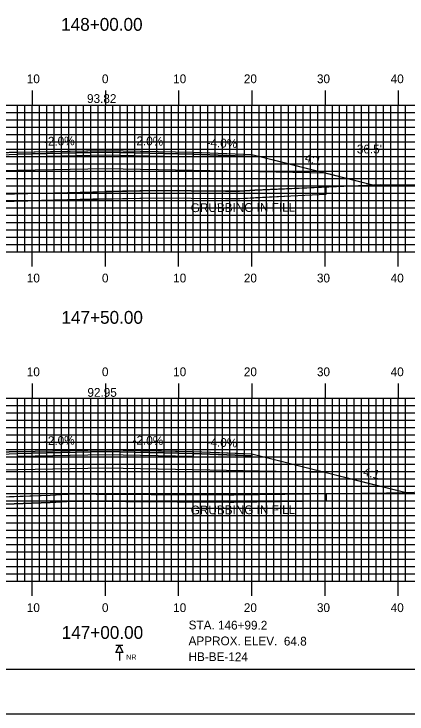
# Model space of a CAD drawing. Extents: x 1777925 to 1778268, y 442591 to 442811.
# Drawn here: x 1778078.3 to 1778132, y 442590.5 to 442686.1 of the extents above; entities that cross this region are included whole.
import ezdxf

# ---------------------------------------------------------------- set-up
doc = ezdxf.new("R2010")
doc.units = 0
for name, color, linetype in [('ANNOTATION', 7, 'Continuous'), ('BORDER', 7, 'Continuous'), ('BORING - NO REFUSAL', 7, 'Continuous'), ('D_Roadway_Centerline', 7, 'Continuous'), ('D_Roadway_Centerline_Text', 7, 'Continuous'), ('D_Roadway_Edge_Shoulder', 7, 'Continuous'), ('D_Roadway_Edge_TW', 7, 'Continuous'), ('D_Roadway_Pavement', 7, 'Continuous'), ('D_Roadway_SlopeLines', 7, 'Continuous'), ('D_Roadway_SubGrade', 7, 'Continuous'), ('D_Text_Standard', 7, 'Continuous'), ('GRUBBING IN FILL', 7, 'Continuous'), ('H_V ANNOTATION', 7, 'Continuous'), ('MAJOR', 7, 'Continuous'), ('MINOR', 7, 'Continuous'), ('PLOT BOUNDARY', 7, 'Continuous'), ('S_Roadway_Centerline', 7, 'Continuous')]:
    doc.layers.add(name, color=color, linetype=linetype)

msp = doc.modelspace()

# ---------------------------------------------------------------- linework, layer by layer
at = {"layer": 'BORDER'}
msp.add_lwpolyline([(1777941.19, 442596.665), (1778261.19, 442596.665), (1778261.19, 442806.665), (1777941.19, 442806.665)], close=True, dxfattribs=at)
at = {"layer": 'BORING - NO REFUSAL'}
for p, q in [((1778093.17, 442599.883), (1778092.21, 442599.883)), ((1778092.69, 442598.924), (1778092.69, 442597.865))]:
    msp.add_line(p, q, dxfattribs=at)
msp.add_lwpolyline([(1778092.69, 442599.883), (1778093.17, 442598.924), (1778092.21, 442598.924)], close=True, dxfattribs=at)
at = {"layer": 'D_Roadway_Centerline'}
for points in [[(1778047.792, 442661.178), (1778058.79, 442663.927), (1778059.609, 442664.132), (1778060.616, 442664.384), (1778070.79, 442666.927), (1778072.648, 442667.002), (1778078.79, 442667.247), (1778085.551, 442667.382), (1778090.79, 442667.487), (1778102.79, 442667.247), (1778110.79, 442666.927), (1778115.943, 442665.639), (1778120.963, 442664.384), (1778121.24, 442664.315), (1778127.328, 442662.793)], [(1778043.66, 442619.27), (1778050.556, 442620.994), (1778058.789, 442623.052), (1778058.79, 442623.052), (1778060.591, 442623.503), (1778060.617, 442623.509), (1778061.603, 442623.756), (1778070.79, 442626.052), (1778078.79, 442626.372), (1778090.79, 442626.612), (1778096.258, 442626.503), (1778102.79, 442626.372), (1778108.725, 442626.135), (1778110.79, 442626.052), (1778120.964, 442623.509), (1778126.145, 442622.214), (1778131.883, 442620.779)]]:
    msp.add_lwpolyline(points, dxfattribs=at)
at = {"layer": 'D_Roadway_Edge_Shoulder'}
for points in [[(1778078.79, 442667.247), (1778070.79, 442666.927), (1778070.79, 442666.677), (1778078.79, 442666.997)], [(1778102.79, 442667.247), (1778110.79, 442666.927), (1778110.79, 442666.677), (1778102.79, 442666.997)], [(1778078.79, 442626.372), (1778070.79, 442626.052), (1778070.79, 442625.802), (1778078.79, 442626.122)], [(1778102.79, 442626.372), (1778110.79, 442626.052), (1778110.79, 442625.802), (1778102.79, 442626.122)]]:
    msp.add_lwpolyline(points, close=True, dxfattribs=at)
at = {"layer": 'D_Roadway_Edge_TW'}
for points in [[(1778078.79, 442666.997), (1778078.79, 442667.247), (1778090.79, 442667.487), (1778102.79, 442667.247), (1778102.79, 442666.997), (1778090.79, 442667.237)], [(1778078.79, 442626.122), (1778078.79, 442626.372), (1778090.79, 442626.612), (1778102.79, 442626.372), (1778102.79, 442626.122), (1778090.79, 442626.362)]]:
    msp.add_lwpolyline(points, close=True, dxfattribs=at)
at = {"layer": 'D_Roadway_Pavement'}
for points in [[(1778078.79, 442666.581), (1778078.79, 442666.997), (1778090.79, 442667.237), (1778102.79, 442666.997), (1778102.79, 442666.581), (1778090.79, 442666.821)], [(1778078.79, 442625.706), (1778078.79, 442626.122), (1778090.79, 442626.362), (1778102.79, 442626.122), (1778102.79, 442625.706), (1778090.79, 442625.946)]]:
    msp.add_lwpolyline(points, close=True, dxfattribs=at)
at = {"layer": 'D_Roadway_SlopeLines'}
for points in [[(1778110.79, 442666.927), (1778120.963, 442664.384), (1778127.328, 442662.793)], [(1778110.79, 442626.052), (1778120.964, 442623.509), (1778131.883, 442620.779)]]:
    msp.add_lwpolyline(points, dxfattribs=at)
at = {"layer": 'D_Roadway_SubGrade'}
for points in [[(1778078.79, 442664.747), (1778060.616, 442664.384), (1778070.79, 442666.927), (1778070.79, 442666.677), (1778078.79, 442666.997), (1778090.79, 442667.237), (1778102.79, 442666.997), (1778110.79, 442666.677), (1778110.79, 442666.927), (1778120.963, 442664.384), (1778102.79, 442664.747), (1778090.79, 442664.987)], [(1778078.79, 442623.872), (1778060.617, 442623.509), (1778070.79, 442626.052), (1778070.79, 442625.802), (1778078.79, 442626.122), (1778090.79, 442626.362), (1778102.79, 442626.122), (1778110.79, 442625.802), (1778110.79, 442626.052), (1778120.964, 442623.509), (1778102.79, 442623.872), (1778090.79, 442624.112)]]:
    msp.add_lwpolyline(points, close=True, dxfattribs=at)
at = {"layer": 'GRUBBING IN FILL'}
for p, q in [((1778120.963, 442661.499), (1778120.963, 442662.499)), ((1778120.963, 442661.499), (1778120.963, 442662.499)), ((1778120.964, 442620.638), (1778120.964, 442619.638)), ((1778120.964, 442620.638), (1778120.964, 442619.638))]:
    msp.add_line(p, q, dxfattribs=at)
for points in [[(1778090.79, 442660.86), (1778097.822, 442661.026), (1778107.179, 442660.909), (1778109.141, 442660.925), (1778110.206, 442660.988), (1778116.117, 442661.275), (1778120.963, 442661.499), (1778120.963, 442662.499), (1778119.806, 442662.446), (1778111.218, 442662.05), (1778109.107, 442661.925), (1778107.182, 442661.909), (1778097.817, 442662.026), (1778090.79, 442661.86)], [(1778090.79, 442660.86), (1778097.822, 442661.026), (1778107.179, 442660.909), (1778109.141, 442660.925), (1778110.206, 442660.988), (1778116.117, 442661.275), (1778120.963, 442661.499), (1778120.963, 442662.499), (1778119.806, 442662.446), (1778111.218, 442662.05), (1778109.107, 442661.925), (1778107.182, 442661.909), (1778097.817, 442662.026), (1778090.79, 442661.86)], [(1778060.616, 442661.205), (1778063.326, 442661.288), (1778065.358, 442661.247), (1778074.613, 442661.472), (1778083.869, 442661.697), (1778090.79, 442661.86), (1778090.79, 442660.86), (1778083.893, 442660.697), (1778074.626, 442660.472), (1778065.36, 442660.247), (1778060.616, 442660.205)], [(1778060.616, 442661.205), (1778063.326, 442661.288), (1778065.358, 442661.247), (1778074.613, 442661.472), (1778083.869, 442661.697), (1778090.79, 442661.86), (1778090.79, 442660.86), (1778083.893, 442660.697), (1778074.626, 442660.472), (1778065.36, 442660.247), (1778060.616, 442660.205)], [(1778060.617, 442619.76), (1778060.942, 442619.759), (1778062.934, 442619.752), (1778067.528, 442619.88), (1778072.121, 442620.007), (1778077.667, 442620.223), (1778083.213, 442620.439), (1778086.468, 442620.6), (1778089.507, 442620.579), (1778090.27, 442620.574), (1778090.79, 442620.57), (1778090.79, 442619.57), (1778086.492, 442619.6), (1778085.99, 442619.572), (1778083.256, 442619.44), (1778072.155, 442619.007), (1778067.551, 442618.88), (1778061.781, 442618.756), (1778060.617, 442618.76)], [(1778060.617, 442619.76), (1778060.942, 442619.759), (1778062.934, 442619.752), (1778067.528, 442619.88), (1778072.121, 442620.007), (1778077.667, 442620.223), (1778083.213, 442620.439), (1778086.468, 442620.6), (1778089.507, 442620.579), (1778090.27, 442620.574), (1778090.79, 442620.57), (1778090.79, 442619.57), (1778086.492, 442619.6), (1778085.99, 442619.572), (1778083.256, 442619.44), (1778072.155, 442619.007), (1778067.551, 442618.88), (1778061.781, 442618.756), (1778060.617, 442618.76)], [(1778090.79, 442620.57), (1778097.046, 442620.527), (1778107.624, 442620.454), (1778118.76, 442620.607), (1778120.964, 442620.638), (1778120.964, 442619.638), (1778114.652, 442619.549), (1778108.339, 442619.459), (1778097.058, 442619.527), (1778090.79, 442619.57)], [(1778090.79, 442620.57), (1778097.046, 442620.527), (1778107.624, 442620.454), (1778118.76, 442620.607), (1778120.964, 442620.638), (1778120.964, 442619.638), (1778114.652, 442619.549), (1778108.339, 442619.459), (1778097.058, 442619.527), (1778090.79, 442619.57)]]:
    msp.add_lwpolyline(points, close=True, dxfattribs=at)
for points in [[(1778060.616, 442660.205), (1778063.331, 442660.288), (1778065.36, 442660.247), (1778083.893, 442660.697), (1778097.822, 442661.026), (1778107.179, 442660.909), (1778109.141, 442660.925), (1778111.271, 442661.052), (1778120.963, 442661.499)], [(1778060.616, 442660.205), (1778063.331, 442660.288), (1778065.36, 442660.247), (1778083.893, 442660.697), (1778097.822, 442661.026), (1778107.179, 442660.909), (1778109.141, 442660.925), (1778111.271, 442661.052), (1778120.963, 442661.499)], [(1778060.617, 442618.76), (1778062.946, 442618.752), (1778072.155, 442619.007), (1778083.256, 442619.44), (1778085.488, 442619.545), (1778086.492, 442619.6), (1778107.624, 442619.454), (1778108.339, 442619.459), (1778120.964, 442619.638)], [(1778060.617, 442618.76), (1778062.946, 442618.752), (1778072.155, 442619.007), (1778083.256, 442619.44), (1778085.488, 442619.545), (1778086.492, 442619.6), (1778107.624, 442619.454), (1778108.339, 442619.459), (1778120.964, 442619.638)]]:
    msp.add_lwpolyline(points, dxfattribs=at)
at = {"layer": 'MAJOR'}
for p, q in [((1778080.79, 442675.669), (1778080.79, 442673.665)), ((1778090.79, 442675.669), (1778090.79, 442673.665)), ((1778100.79, 442675.669), (1778100.79, 442673.665)), ((1778110.79, 442675.669), (1778110.79, 442673.665)), ((1778120.79, 442675.669), (1778120.79, 442673.665)), ((1778130.79, 442675.669), (1778130.79, 442673.665)), ((1777950.79, 442673.665), (1778230.79, 442673.665)), ((1777950.79, 442673.665), (1778230.79, 442673.665)), ((1778080.79, 442653.665), (1778080.79, 442673.665)), ((1778090.79, 442653.665), (1778090.79, 442673.665)), ((1778100.79, 442653.665), (1778100.79, 442673.665)), ((1778110.79, 442653.665), (1778110.79, 442673.665)), ((1778120.79, 442653.665), (1778120.79, 442673.665)), ((1778130.79, 442653.665), (1778130.79, 442673.665)), ((1777950.79, 442668.665), (1778230.79, 442668.665)), ((1777950.79, 442663.665), (1778230.79, 442663.665)), ((1777950.79, 442658.665), (1778230.79, 442658.665)), ((1777950.79, 442653.665), (1778230.79, 442653.665)), ((1777950.79, 442653.665), (1778230.79, 442653.665)), ((1778080.79, 442651.661), (1778080.79, 442653.665)), ((1778090.79, 442651.661), (1778090.79, 442653.665)), ((1778100.79, 442651.661), (1778100.79, 442653.665)), ((1778110.79, 442651.661), (1778110.79, 442653.665)), ((1778120.79, 442651.661), (1778120.79, 442653.665)), ((1778130.79, 442651.661), (1778130.79, 442653.665)), ((1778080.79, 442635.669), (1778080.79, 442633.665)), ((1778090.79, 442635.669), (1778090.79, 442633.665)), ((1778100.79, 442635.669), (1778100.79, 442633.665)), ((1778110.79, 442635.669), (1778110.79, 442633.665)), ((1778120.79, 442635.669), (1778120.79, 442633.665)), ((1778130.79, 442635.669), (1778130.79, 442633.665)), ((1777950.79, 442633.665), (1778230.79, 442633.665)), ((1777950.79, 442633.665), (1778230.79, 442633.665)), ((1778080.79, 442608.665), (1778080.79, 442633.665)), ((1778090.79, 442608.665), (1778090.79, 442633.665)), ((1778100.79, 442608.665), (1778100.79, 442633.665)), ((1778110.79, 442608.665), (1778110.79, 442633.665)), ((1778120.79, 442608.665), (1778120.79, 442633.665)), ((1778130.79, 442608.665), (1778130.79, 442633.665)), ((1777950.79, 442628.665), (1778230.79, 442628.665)), ((1777950.79, 442623.665), (1778230.79, 442623.665)), ((1777950.79, 442618.665), (1778230.79, 442618.665)), ((1777950.79, 442613.665), (1778230.79, 442613.665)), ((1777950.79, 442608.665), (1778230.79, 442608.665)), ((1777950.79, 442608.665), (1778230.79, 442608.665)), ((1778080.79, 442606.661), (1778080.79, 442608.665)), ((1778090.79, 442606.661), (1778090.79, 442608.665)), ((1778100.79, 442606.661), (1778100.79, 442608.665)), ((1778110.79, 442606.661), (1778110.79, 442608.665)), ((1778120.79, 442606.661), (1778120.79, 442608.665)), ((1778130.79, 442606.661), (1778130.79, 442608.665))]:
    msp.add_line(p, q, dxfattribs=at)
at = {"layer": 'MINOR'}
for p, q in [((1778078.79, 442653.665), (1778078.79, 442673.665)), ((1778079.79, 442653.665), (1778079.79, 442673.665)), ((1778081.79, 442653.665), (1778081.79, 442673.665)), ((1778082.79, 442653.665), (1778082.79, 442673.665)), ((1778083.79, 442653.665), (1778083.79, 442673.665)), ((1778084.79, 442653.665), (1778084.79, 442673.665)), ((1778085.79, 442653.665), (1778085.79, 442673.665)), ((1778086.79, 442653.665), (1778086.79, 442673.665)), ((1778087.79, 442653.665), (1778087.79, 442673.665)), ((1778088.79, 442653.665), (1778088.79, 442673.665)), ((1778089.79, 442653.665), (1778089.79, 442673.665)), ((1778091.79, 442653.665), (1778091.79, 442673.665)), ((1778092.79, 442653.665), (1778092.79, 442673.665)), ((1778093.79, 442653.665), (1778093.79, 442673.665)), ((1778094.79, 442653.665), (1778094.79, 442673.665)), ((1778095.79, 442653.665), (1778095.79, 442673.665)), ((1778096.79, 442653.665), (1778096.79, 442673.665)), ((1778097.79, 442653.665), (1778097.79, 442673.665)), ((1778098.79, 442653.665), (1778098.79, 442673.665)), ((1778099.79, 442653.665), (1778099.79, 442673.665)), ((1778101.79, 442653.665), (1778101.79, 442673.665)), ((1778102.79, 442653.665), (1778102.79, 442673.665)), ((1778103.79, 442653.665), (1778103.79, 442673.665)), ((1778104.79, 442653.665), (1778104.79, 442673.665)), ((1778105.79, 442653.665), (1778105.79, 442673.665)), ((1778106.79, 442653.665), (1778106.79, 442673.665)), ((1778107.79, 442653.665), (1778107.79, 442673.665)), ((1778108.79, 442653.665), (1778108.79, 442673.665)), ((1778109.79, 442653.665), (1778109.79, 442673.665)), ((1778111.79, 442653.665), (1778111.79, 442673.665)), ((1778112.79, 442653.665), (1778112.79, 442673.665)), ((1778113.79, 442653.665), (1778113.79, 442673.665)), ((1778114.79, 442653.665), (1778114.79, 442673.665)), ((1778115.79, 442653.665), (1778115.79, 442673.665)), ((1778116.79, 442653.665), (1778116.79, 442673.665)), ((1778117.79, 442653.665), (1778117.79, 442673.665)), ((1778118.79, 442653.665), (1778118.79, 442673.665)), ((1778119.79, 442653.665), (1778119.79, 442673.665)), ((1778121.79, 442653.665), (1778121.79, 442673.665)), ((1778122.79, 442653.665), (1778122.79, 442673.665)), ((1778123.79, 442653.665), (1778123.79, 442673.665)), ((1778124.79, 442653.665), (1778124.79, 442673.665)), ((1778125.79, 442653.665), (1778125.79, 442673.665)), ((1778126.79, 442653.665), (1778126.79, 442673.665)), ((1778127.79, 442653.665), (1778127.79, 442673.665)), ((1778128.79, 442653.665), (1778128.79, 442673.665)), ((1778129.79, 442653.665), (1778129.79, 442673.665)), ((1778131.79, 442653.665), (1778131.79, 442673.665)), ((1777950.79, 442672.665), (1778230.79, 442672.665)), ((1777950.79, 442671.665), (1778230.79, 442671.665)), ((1777950.79, 442670.665), (1778230.79, 442670.665)), ((1777950.79, 442669.665), (1778230.79, 442669.665)), ((1777950.79, 442667.665), (1778230.79, 442667.665)), ((1777950.79, 442666.665), (1778230.79, 442666.665)), ((1777950.79, 442665.665), (1778230.79, 442665.665)), ((1777950.79, 442664.665), (1778230.79, 442664.665)), ((1777950.79, 442662.665), (1778230.79, 442662.665)), ((1777950.79, 442661.665), (1778230.79, 442661.665)), ((1777950.79, 442660.665), (1778230.79, 442660.665)), ((1777950.79, 442659.665), (1778230.79, 442659.665)), ((1777950.79, 442657.665), (1778230.79, 442657.665)), ((1777950.79, 442656.665), (1778230.79, 442656.665)), ((1777950.79, 442655.665), (1778230.79, 442655.665)), ((1777950.79, 442654.665), (1778230.79, 442654.665)), ((1778078.79, 442608.665), (1778078.79, 442633.665)), ((1778079.79, 442608.665), (1778079.79, 442633.665)), ((1778081.79, 442608.665), (1778081.79, 442633.665)), ((1778082.79, 442608.665), (1778082.79, 442633.665)), ((1778083.79, 442608.665), (1778083.79, 442633.665)), ((1778084.79, 442608.665), (1778084.79, 442633.665)), ((1778085.79, 442608.665), (1778085.79, 442633.665)), ((1778086.79, 442608.665), (1778086.79, 442633.665)), ((1778087.79, 442608.665), (1778087.79, 442633.665)), ((1778088.79, 442608.665), (1778088.79, 442633.665)), ((1778089.79, 442608.665), (1778089.79, 442633.665)), ((1778091.79, 442608.665), (1778091.79, 442633.665)), ((1778092.79, 442608.665), (1778092.79, 442633.665)), ((1778093.79, 442608.665), (1778093.79, 442633.665)), ((1778094.79, 442608.665), (1778094.79, 442633.665)), ((1778095.79, 442608.665), (1778095.79, 442633.665)), ((1778096.79, 442608.665), (1778096.79, 442633.665)), ((1778097.79, 442608.665), (1778097.79, 442633.665)), ((1778098.79, 442608.665), (1778098.79, 442633.665)), ((1778099.79, 442608.665), (1778099.79, 442633.665)), ((1778101.79, 442608.665), (1778101.79, 442633.665)), ((1778102.79, 442608.665), (1778102.79, 442633.665)), ((1778103.79, 442608.665), (1778103.79, 442633.665)), ((1778104.79, 442608.665), (1778104.79, 442633.665)), ((1778105.79, 442608.665), (1778105.79, 442633.665)), ((1778106.79, 442608.665), (1778106.79, 442633.665)), ((1778107.79, 442608.665), (1778107.79, 442633.665)), ((1778108.79, 442608.665), (1778108.79, 442633.665)), ((1778109.79, 442608.665), (1778109.79, 442633.665)), ((1778111.79, 442608.665), (1778111.79, 442633.665)), ((1778112.79, 442608.665), (1778112.79, 442633.665)), ((1778113.79, 442608.665), (1778113.79, 442633.665)), ((1778114.79, 442608.665), (1778114.79, 442633.665)), ((1778115.79, 442608.665), (1778115.79, 442633.665)), ((1778116.79, 442608.665), (1778116.79, 442633.665)), ((1778117.79, 442608.665), (1778117.79, 442633.665)), ((1778118.79, 442608.665), (1778118.79, 442633.665)), ((1778119.79, 442608.665), (1778119.79, 442633.665)), ((1778121.79, 442608.665), (1778121.79, 442633.665)), ((1778122.79, 442608.665), (1778122.79, 442633.665)), ((1778123.79, 442608.665), (1778123.79, 442633.665)), ((1778124.79, 442608.665), (1778124.79, 442633.665)), ((1778125.79, 442608.665), (1778125.79, 442633.665)), ((1778126.79, 442608.665), (1778126.79, 442633.665)), ((1778127.79, 442608.665), (1778127.79, 442633.665)), ((1778128.79, 442608.665), (1778128.79, 442633.665)), ((1778129.79, 442608.665), (1778129.79, 442633.665)), ((1778131.79, 442608.665), (1778131.79, 442633.665)), ((1777950.79, 442632.665), (1778230.79, 442632.665)), ((1777950.79, 442631.665), (1778230.79, 442631.665)), ((1777950.79, 442630.665), (1778230.79, 442630.665)), ((1777950.79, 442629.665), (1778230.79, 442629.665)), ((1777950.79, 442627.665), (1778230.79, 442627.665)), ((1777950.79, 442626.665), (1778230.79, 442626.665)), ((1777950.79, 442625.665), (1778230.79, 442625.665)), ((1777950.79, 442624.665), (1778230.79, 442624.665)), ((1777950.79, 442622.665), (1778230.79, 442622.665)), ((1777950.79, 442621.665), (1778230.79, 442621.665)), ((1777950.79, 442620.665), (1778230.79, 442620.665)), ((1777950.79, 442619.665), (1778230.79, 442619.665)), ((1777950.79, 442617.665), (1778230.79, 442617.665)), ((1777950.79, 442616.665), (1778230.79, 442616.665)), ((1777950.79, 442615.665), (1778230.79, 442615.665)), ((1777950.79, 442614.665), (1778230.79, 442614.665)), ((1777950.79, 442612.665), (1778230.79, 442612.665)), ((1777950.79, 442611.665), (1778230.79, 442611.665)), ((1777950.79, 442610.665), (1778230.79, 442610.665)), ((1777950.79, 442609.665), (1778230.79, 442609.665))]:
    msp.add_line(p, q, dxfattribs=at)
at = {"layer": 'PLOT BOUNDARY'}
msp.add_lwpolyline([(1777925.003, 442590.547), (1778265.003, 442590.547), (1778265.003, 442810.547), (1777925.003, 442810.547)], close=True, dxfattribs=at)
at = {"layer": 'S_Roadway_Centerline'}
for points in [[(1777950.79, 442659.341), (1777957.637, 442659.573), (1777969.437, 442659.353), (1777970.922, 442659.383), (1777992.887, 442659.856), (1778004.185, 442659.95), (1778017.022, 442660.194), (1778027.551, 442660.534), (1778038.131, 442661.083), (1778040.821, 442661.181), (1778050.827, 442661.177), (1778061.024, 442661.218), (1778063.326, 442661.288), (1778065.358, 442661.247), (1778083.869, 442661.697), (1778097.817, 442662.026), (1778107.182, 442661.909), (1778109.107, 442661.925), (1778111.218, 442662.05), (1778128.394, 442662.842), (1778134.182, 442662.79)], [(1777950.79, 442617.395), (1777956.017, 442617.414), (1777972.056, 442617.846), (1777979.693, 442617.903), (1777987.767, 442618.089), (1777991.687, 442618.08), (1777995.058, 442618.124), (1778011.222, 442618.225), (1778018.028, 442618.392), (1778036.183, 442618.991), (1778037.813, 442619.081), (1778039.538, 442619.137), (1778058.95, 442619.765), (1778062.934, 442619.752), (1778072.121, 442620.007), (1778083.213, 442620.439), (1778085.437, 442620.544), (1778086.468, 442620.6), (1778107.624, 442620.454), (1778108.328, 442620.459), (1778129.191, 442620.755), (1778131.694, 442620.772), (1778142.049, 442621.162)]]:
    msp.add_lwpolyline(points, dxfattribs=at)

# ---------------------------------------------------------------- texts
at = {"layer": 'ANNOTATION'}
for s, rotation, p in [('-2.0%', 1.14576, (1778082.396, 442668.12)), ('-2.0%', 358.85424, (1778094.476, 442668.214)), ('-4.0%', 357.70947, (1778104.582, 442667.977)), ('4:1', 345.96523, (1778117.943, 442665.982)), ('-2.0%', 1.14576, (1778082.396, 442627.245)), ('-2.0%', 358.85424, (1778094.476, 442627.339)), ('-4.0%', 357.70927, (1778104.582, 442627.102)), ('4:1', 345.96202, (1778125.929, 442623.129))]:
    msp.add_text(s, height=1.2, rotation=rotation, dxfattribs=at).set_placement(p)
at = {"layer": 'BORING - NO REFUSAL'}
for s, p in [('STA. 146+99.2', (1778102.151, 442602.1)), ('APPROX. ELEV.  64.8', (1778102.144, 442599.94)), ('HB-BE-124', (1778102.137, 442597.78))]:
    msp.add_text(s, height=1.2, rotation=359.81416, dxfattribs=at).set_placement(p)
msp.add_text('NR', height=0.6998, dxfattribs=at).set_placement((1778093.623, 442597.968))
at = {"layer": 'D_Roadway_Centerline'}
for s, p in [('C', (1778090.785, 442667.487)), ('L', (1778090.79, 442667.48)), ('C', (1778090.785, 442626.612)), ('L', (1778090.79, 442626.605))]:
    msp.add_text(s, height=0.0146, dxfattribs=at).set_placement(p)
at = {"layer": 'D_Roadway_Centerline_Text'}
for s, p in [('93.82', (1778088.27, 442673.964)), ('92.95', (1778088.323, 442633.851))]:
    msp.add_text(s, height=1.2, dxfattribs=at).set_placement(p)
at = {"layer": 'D_Text_Standard'}
msp.add_text("36.5'", height=1.2, dxfattribs=at).set_placement((1778125.139, 442667.076))
at = {"layer": 'GRUBBING IN FILL'}
for p in [(1778102.45, 442659.066), (1778102.45, 442617.795)]:
    msp.add_text('GRUBBING IN FILL', height=1.2, rotation=0.24521, dxfattribs=at).set_placement(p)
at = {"layer": 'H_V ANNOTATION'}
for s, height, p in [('148+00.00', 1.75, (1778084.735, 442683.821)), ('10', 1.2, (1778080.041, 442676.665)), ('0', 1.2, (1778090.308, 442676.665)), ('10', 1.2, (1778100.041, 442676.665)), ('20', 1.2, (1778109.698, 442676.665)), ('30', 1.2, (1778119.687, 442676.665)), ('40', 1.2, (1778129.762, 442676.665)), ('10', 1.2, (1778080.041, 442649.465)), ('0', 1.2, (1778090.308, 442649.465)), ('10', 1.2, (1778100.041, 442649.465)), ('20', 1.2, (1778109.698, 442649.465)), ('30', 1.2, (1778119.687, 442649.465)), ('40', 1.2, (1778129.762, 442649.465)), ('147+50.00', 1.75, (1778084.781, 442643.821)), ('10', 1.2, (1778080.041, 442636.665)), ('0', 1.2, (1778090.308, 442636.665)), ('10', 1.2, (1778100.041, 442636.665)), ('20', 1.2, (1778109.698, 442636.665)), ('30', 1.2, (1778119.687, 442636.665)), ('40', 1.2, (1778129.762, 442636.665)), ('10', 1.2, (1778080.041, 442604.465)), ('0', 1.2, (1778090.308, 442604.465)), ('10', 1.2, (1778100.041, 442604.465)), ('20', 1.2, (1778109.698, 442604.465)), ('30', 1.2, (1778119.687, 442604.465)), ('40', 1.2, (1778129.762, 442604.465)), ('147+00.00', 1.75, (1778084.813, 442600.802))]:
    msp.add_text(s, height=height, dxfattribs=at).set_placement(p)

doc.saveas('drawing.dxf')
